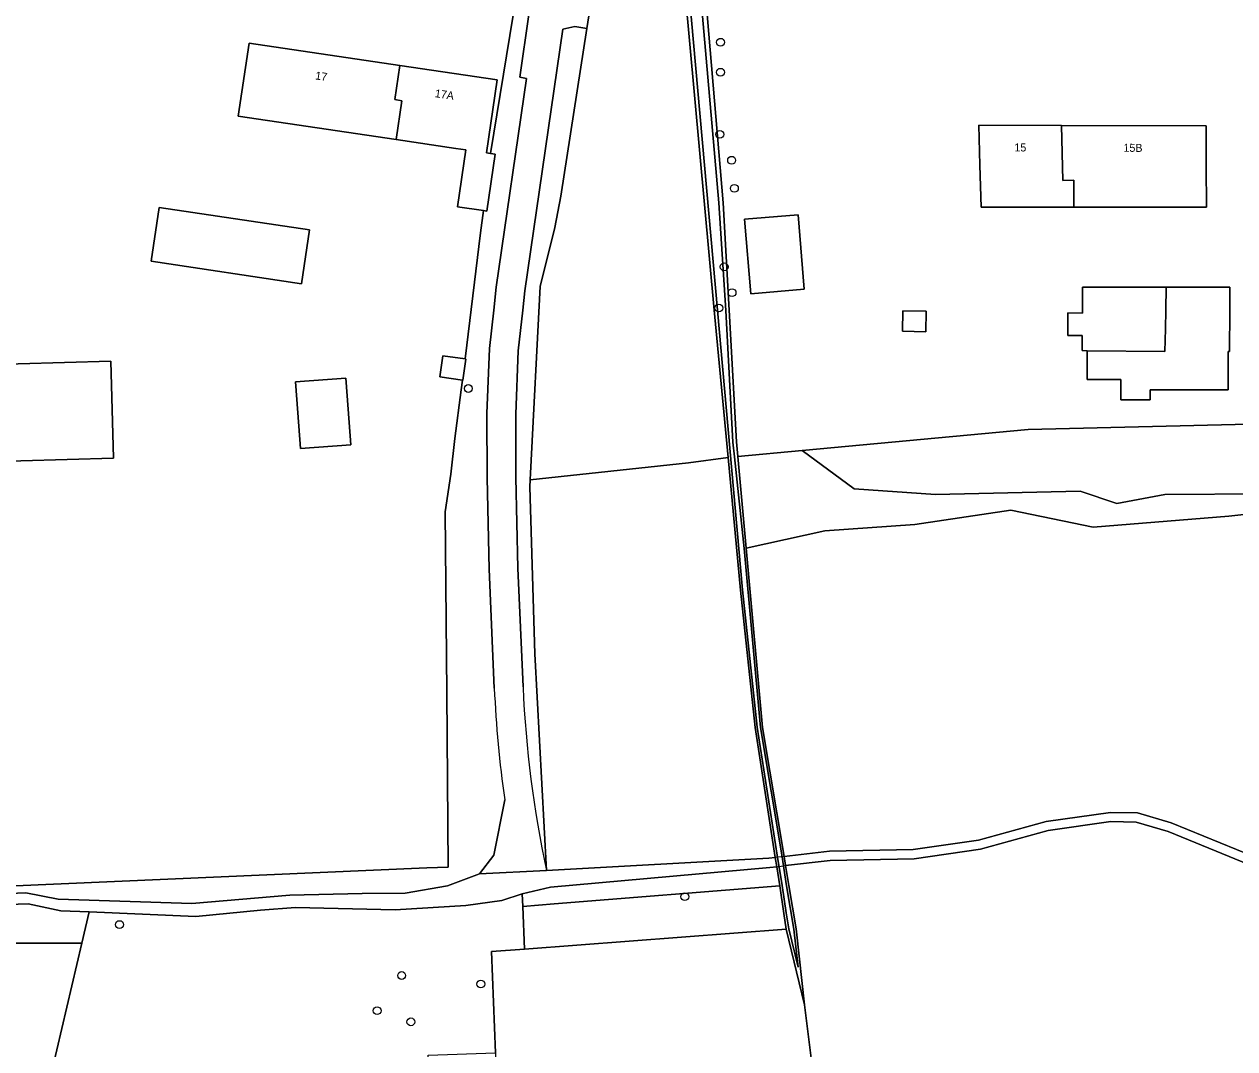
# Model space of a CAD drawing. Extents: x 162510 to 163918, y 388494 to 389774.
# Drawn here: x 162616.6 to 162767.9, y 388907.7 to 389035.7 of the extents above; entities that cross this region are included whole.
import ezdxf

# ---------------------------------------------------------------- set-up
doc = ezdxf.new("R2010")
doc.units = 0
for name, color, linetype in [('IMGEO_Boom', 7, 'Continuous'), ('IMGEO_Erf', 7, 'Continuous'), ('IMGEO_Grasland_agrarisch', 7, 'Continuous'), ('IMGEO_Grasland_overig', 7, 'Continuous'), ('IMGEO_Groenvoorziening', 7, 'Continuous'), ('IMGEO_Hek', 7, 'Continuous'), ('IMGEO_Loofbos', 7, 'Continuous'), ('IMGEO_Oever', 7, 'Continuous'), ('IMGEO_Pand', 7, 'Continuous'), ('IMGEO_Pand_nummerreeks', 7, 'Continuous'), ('IMGEO_Rijbaan_lokaal_gesloten', 7, 'Continuous'), ('IMGEO_Rijbaan_lokaal_halfverhard', 7, 'Continuous'), ('IMGEO_Rijbaan_lokaal_onverhard', 7, 'Continuous'), ('IMGEO_Waterloop', 7, 'Continuous')]:
    doc.layers.add(name, color=color, linetype=linetype)

msp = doc.modelspace()

# ---------------------------------------------------------------- linework, layer by layer
at = {"layer": 'IMGEO_Boom'}
for centre in [(162703.65, 389033.47), (162703.64, 389029.72), (162703.56, 389021.96), (162705.03, 389018.72), (162705.38, 389015.21), (162704.1, 389005.4), (162705.09, 389002.17), (162703.44, 389000.25), (162672.12, 388990.19), (162699.18, 388926.67), (162628.52, 388923.18), (162663.79, 388916.81), (162673.68, 388915.75), (162660.72, 388912.42), (162664.94, 388911.02)]:
    msp.add_circle(centre, 0.489, dxfattribs=at)
at = {"layer": 'IMGEO_Erf'}
for points in [[(162663.55, 389030.58), (162675.73, 389028.77), (162674.38, 389019.65), (162674.91, 389019.57), (162678.51, 389041.74), (162678.36, 389043.46), (162678.63, 389045.93)], [(162614.58, 388927.98), (162666.94, 388930.26), (162669.61, 388930.37), (162669.42, 388952.14), (162669.22, 388974.79), (162669.94, 388979.5), (162670.45, 388983.96), (162671.23, 388990.04), (162671.38, 388991.23), (162668.55, 388991.63), (162668.93, 388994.29), (162671.71, 388993.89), (162673.66, 389009.65), (162674, 389012.43), (162670.77, 389012.9), (162671.81, 389020.03), (162670.57, 389020.21), (162663.1, 389021.32), (162643.36, 389024.24), (162644.71, 389033.37), (162663.55, 389030.58)]]:
    msp.add_lwpolyline(points, dxfattribs=at)
for points in [[(162686.13, 389044.35), (162685.88, 389043.41), (162685.83, 389042.01), (162686.33, 389040.71), (162687.77, 389040.48), (162686.95, 389035.21), (162683.69, 389014.23), (162682.95, 389010.32), (162681.09, 389002.93), (162679.91, 388979.62), (162679.87, 388978.79), (162699.64, 388980.89), (162704.58, 388981.58), (162702.83, 389000), (162698.61, 389046.48), (162692.16, 389046.72), (162688.55, 389045.49), (162686.9, 389045.33)], [(162770.17, 389041.8), (162769.26, 389041.78), (162764.94, 389041.67), (162762.37, 389041.61), (162743.97, 389041.23), (162741.47, 389041.26), (162723.17, 389042.73), (162708.72, 389044.45), (162703.43, 389045.08), (162701.26, 389045.33), (162703.97, 389013.41), (162704.72, 389000), (162705.65, 388983.52), (162705.82, 388981.68), (162713.87, 388982.43), (162742.1, 388985.07), (162771.44, 388985.76), (162771.12, 389000)], [(162735.92, 389023.09), (162746.26, 389023.06), (162764.35, 389023.01), (162764.37, 389018.01), (162764.39, 389012.86), (162747.8, 389012.87), (162736.21, 389012.87), (162736.06, 389018.09)], [(162651.27, 389003.29), (162632.47, 389006.11), (162633.47, 389012.82), (162652.27, 389010.01)], [(162713.34, 389011.92), (162714.12, 389002.59), (162707.43, 389002.03), (162706.65, 389011.36)], [(162759.37, 389002.84), (162767.29, 389002.84), (162767.29, 389000), (162767.28, 388994.8), (162767.11, 388994.8), (162767.11, 388990.02), (162757.34, 388990.02), (162757.34, 388988.78), (162753.67, 388988.78), (162753.67, 388991.31), (162749.46, 388991.32), (162749.46, 388994.92), (162748.86, 388994.93), (162748.86, 388996.83), (162747.05, 388996.83), (162747.05, 388999.63), (162748.9, 388999.62), (162748.9, 389000), (162748.91, 389002.85)], [(162726.4, 388997.34), (162726.45, 388999.91), (162729.35, 388999.85), (162729.3, 388997.29)], [(162627.44, 388993.6), (162627.78, 388981.47), (162610.37, 388980.99), (162610.03, 388993.12)], [(162656.81, 388991.5), (162657.1, 388987.61), (162657.42, 388983.16), (162651.14, 388982.7), (162650.81, 388987.15), (162650.53, 388991.04)]]:
    msp.add_lwpolyline(points, close=True, dxfattribs=at)
at = {"layer": 'IMGEO_Grasland_agrarisch'}
msp.add_lwpolyline([(162710.49, 388931.57), (162707.98, 388947.83), (162706.16, 388965), (162704.58, 388981.58), (162699.64, 388980.89), (162679.87, 388978.79), (162679.83, 388977.88), (162680.42, 388957.01), (162681.91, 388929.94), (162709.68, 388931.47)], close=True, dxfattribs=at)
at = {"layer": 'IMGEO_Grasland_overig'}
for points in [[(162679.91, 388979.62), (162681.09, 389002.93), (162682.95, 389010.32), (162683.69, 389014.23), (162686.95, 389035.21), (162685.42, 389035.44), (162683.94, 389035.1), (162679.2, 389002.39), (162678.93, 389000), (162678.37, 388994.91), (162678.05, 388987), (162678.07, 388979.08), (162678.32, 388967.74), (162678.96, 388952.88)], [(162681.91, 388929.94), (162680.42, 388957.01), (162679.83, 388977.88), (162679.87, 388978.79), (162679.91, 388979.62)]]:
    msp.add_lwpolyline(points, dxfattribs=at)
for points in [[(162771.63, 388977.03), (162759.18, 388976.94), (162753.18, 388975.82), (162748.59, 388977.36), (162730.5, 388976.95), (162720.37, 388977.67), (162713.87, 388982.43), (162705.82, 388981.68), (162706.86, 388970.23), (162716.69, 388972.41), (162727.93, 388973.18), (162739.95, 388975), (162750.24, 388972.84), (162767.18, 388974.22), (162771.68, 388974.74)], [(162679.15, 388920.12), (162711.87, 388922.6), (162711.57, 388924.58), (162711.04, 388928.02), (162682.87, 388925.77), (162678.93, 388925.46)], [(162624.73, 388924.76), (162621.18, 388924.91), (162617.1, 388925.78), (162600.99, 388925.22), (162598.94, 388924.91), (162594.58, 388923.48), (162585.28, 388919.42), (162574.62, 388915.42), (162562.97, 388909.61), (162563.08, 388907.3), (162564.14, 388907.35), (162579.19, 388908.49), (162582.54, 388908.67), (162586.02, 388909.21), (162589.2, 388911.23), (162591.28, 388913.31), (162595.02, 388915.56), (162602.02, 388918.9), (162607.31, 388919.84), (162614.86, 388920.84), (162623.8, 388920.84)]]:
    msp.add_lwpolyline(points, close=True, dxfattribs=at)
msp.add_arc((162817.58, 388959.03), 138.76, 182.5435, 192.1018, dxfattribs=at)
at = {"layer": 'IMGEO_Groenvoorziening'}
for points in [[(162678.51, 389041.74), (162674.91, 389019.57), (162675.47, 389019.49), (162674.43, 389012.36), (162674, 389012.43), (162673.66, 389009.65), (162671.71, 388993.89), (162671.83, 388993.87), (162671.45, 388991.22), (162671.38, 388991.23), (162671.23, 388990.04), (162670.45, 388983.96), (162669.94, 388979.5), (162669.22, 388974.79), (162669.42, 388952.14), (162669.61, 388930.37), (162666.94, 388930.26), (162614.58, 388927.98)], [(162675.31, 389000), (162675.62, 389002.84), (162679.41, 389028.93), (162678.56, 389029.1), (162679.69, 389036.94)], [(162675.36, 388952.72), (162674.72, 388967.62), (162674.46, 388979.04), (162674.45, 388987.07), (162674.78, 388995.18), (162675.31, 389000)], [(162600.93, 388926.51), (162616.81, 388927.16), (162620.85, 388926.35), (162637.57, 388925.81), (162649.8, 388926.85), (162658.85, 388927.06), (162664.24, 388927.09), (162669.52, 388928.04), (162673.53, 388929.52), (162675.3, 388931.84), (162676.67, 388938.79)]]:
    msp.add_lwpolyline(points, dxfattribs=at)
for points in [[(162713.87, 388982.43), (162720.37, 388977.67), (162730.5, 388976.95), (162748.59, 388977.36), (162753.18, 388975.82), (162759.18, 388976.94), (162771.63, 388977.03), (162771.44, 388985.76), (162742.1, 388985.07)], [(162714.16, 388913.17), (162711.87, 388922.6), (162679.15, 388920.12), (162675.02, 388919.81), (162675.53, 388907.17), (162677.2, 388865.09), (162720.77, 388860.13)]]:
    msp.add_lwpolyline(points, close=True, dxfattribs=at)
msp.add_arc((162817.7, 388959.04), 142.47, 182.544, 188.1712, dxfattribs=at)
at = {"layer": 'IMGEO_Hek'}
for points in [[(162670.45, 388983.96), (162671.23, 388990.04)], [(162669.94, 388979.5), (162669.22, 388974.79), (162669.42, 388952.14)], [(162669.42, 388952.14), (162669.61, 388930.37), (162666.94, 388930.26)], [(162666.94, 388930.26), (162614.58, 388927.98)], [(162682.87, 388925.77), (162711.04, 388928.02)], [(162678.93, 388925.46), (162682.87, 388925.77)]]:
    msp.add_lwpolyline(points, dxfattribs=at)
at = {"layer": 'IMGEO_Loofbos'}
for points in [[(162717.28, 388932.34), (162727.74, 388932.58), (162735.9, 388933.72), (162744.35, 388936.06), (162752.38, 388937.21), (162755.76, 388937.15), (162759.98, 388935.89), (162774.27, 388930.05), (162780.17, 388928.65), (162779.73, 388931.61), (162777.31, 388948.04), (162777.42, 388954.51), (162773.99, 388957.61), (162771.8, 388969.76), (162771.68, 388974.74), (162767.18, 388974.22), (162750.24, 388972.84), (162739.95, 388975), (162727.93, 388973.18), (162716.69, 388972.41), (162706.86, 388970.23), (162708.89, 388947.83), (162711.59, 388931.69)], [(162773.92, 388928.95), (162759.59, 388934.8), (162755.59, 388936), (162752.45, 388936.05), (162744.59, 388934.93), (162736.14, 388932.59), (162727.84, 388931.42), (162717.36, 388931.19), (162711.78, 388930.55), (162712.19, 388928.08), (162713.1, 388922.66), (162713.16, 388922.29), (162714.16, 388913.17), (162720.77, 388860.13), (162742.46, 388857.66), (162798.24, 388863.43), (162799.04, 388869.27), (162799.08, 388869.54), (162788.74, 388870.61), (162788.35, 388873.03), (162780.35, 388927.41)], [(162709.8, 388930.32), (162682.38, 388927.84), (162678.87, 388927.02), (162678.93, 388925.46), (162682.87, 388925.77), (162711.04, 388928.02), (162710.67, 388930.42)], [(162623.8, 388920.84), (162620.04, 388904.86), (162667.1, 388906.56), (162667.1, 388906.86), (162675.53, 388907.17), (162675.02, 388919.81), (162679.15, 388920.12), (162678.93, 388925.46), (162678.87, 388927.02), (162676.3, 388926.18), (162671.81, 388925.58), (162662.99, 388925.04), (162650.5, 388925.3), (162646.15, 388924.99), (162638.07, 388924.19), (162624.73, 388924.76)], [(162573.16, 388903.16), (162620.04, 388904.86), (162623.8, 388920.84), (162614.86, 388920.84), (162607.31, 388919.84), (162602.02, 388918.9), (162595.02, 388915.56), (162591.28, 388913.31), (162589.2, 388911.23), (162586.02, 388909.21), (162582.54, 388908.67), (162579.19, 388908.49), (162564.14, 388907.35), (162564.26, 388902.98), (162570.6, 388903.11)]]:
    msp.add_lwpolyline(points, close=True, dxfattribs=at)
at = {"layer": 'IMGEO_Oever'}
for points in [[(162705.82, 388981.68), (162705.65, 388983.52), (162704.72, 389000), (162703.97, 389013.41), (162701.26, 389045.33), (162698.61, 389046.48), (162702.83, 389000), (162704.58, 388981.58), (162706.16, 388965), (162707.98, 388947.83), (162710.49, 388931.57), (162710.67, 388930.42), (162711.04, 388928.02), (162711.57, 388924.58), (162711.87, 388922.6), (162714.16, 388913.17), (162713.16, 388922.29), (162713.1, 388922.66), (162712.19, 388928.08), (162711.78, 388930.55), (162711.59, 388931.69), (162708.89, 388947.83), (162706.86, 388970.23)], [(162711.3, 388931.91), (162711.89, 388928.03), (162712.79, 388922.61), (162712.86, 388922.24), (162713.34, 388917.85), (162712.17, 388922.65), (162711.87, 388924.63), (162711.35, 388928.07), (162710.71, 388931.84), (162708.23, 388947.87), (162706.41, 388965.03), (162703.27, 388999.99), (162699.2, 389045.57), (162700.69, 389044.87), (162703.45, 389013.38), (162704.29, 388999.94), (162705.19, 388983.48), (162705.41, 388981.63), (162706.61, 388970.21), (162708.64, 388947.8)]]:
    msp.add_lwpolyline(points, close=True, dxfattribs=at)
at = {"layer": 'IMGEO_Pand'}
for points in [[(162663.1, 389021.32), (162663.8, 389026.17), (162662.94, 389026.3), (162663.55, 389030.58), (162644.71, 389033.37), (162643.36, 389024.24)], [(162663.1, 389021.32), (162670.57, 389020.21), (162671.81, 389020.03), (162670.77, 389012.9), (162674, 389012.43), (162674.43, 389012.36), (162675.47, 389019.49), (162674.91, 389019.57), (162674.38, 389019.65), (162675.73, 389028.77), (162663.55, 389030.58), (162662.94, 389026.3), (162663.8, 389026.17)], [(162747.8, 389012.87), (162747.81, 389016.22), (162746.43, 389016.18), (162746.26, 389023.06), (162735.92, 389023.09), (162736.06, 389018.09), (162736.21, 389012.87)], [(162747.8, 389012.87), (162764.39, 389012.86), (162764.37, 389018.01), (162764.35, 389023.01), (162746.26, 389023.06), (162746.43, 389016.18), (162747.81, 389016.22)], [(162651.27, 389003.29), (162652.27, 389010.01), (162633.47, 389012.82), (162632.47, 389006.11)], [(162713.34, 389011.92), (162706.65, 389011.36), (162707.43, 389002.03), (162714.12, 389002.59)], [(162759.37, 389002.84), (162748.91, 389002.85), (162748.9, 389000), (162748.9, 388999.62), (162747.05, 388999.63), (162747.05, 388996.83), (162748.86, 388996.83), (162748.86, 388994.93), (162749.46, 388994.92), (162759.18, 388994.83), (162759.25, 388997.67), (162759.3, 389000)], [(162759.37, 389002.84), (162759.3, 389000), (162759.25, 388997.67), (162759.18, 388994.83), (162749.46, 388994.92), (162749.46, 388991.32), (162753.67, 388991.31), (162753.67, 388988.78), (162757.34, 388988.78), (162757.34, 388990.02), (162767.11, 388990.02), (162767.11, 388994.8), (162767.28, 388994.8), (162767.29, 389000), (162767.29, 389002.84)], [(162726.4, 388997.34), (162729.3, 388997.29), (162729.35, 388999.85), (162726.45, 388999.91)], [(162671.71, 388993.89), (162668.93, 388994.29), (162668.55, 388991.63), (162671.38, 388991.23), (162671.45, 388991.22), (162671.83, 388993.87)], [(162627.44, 388993.6), (162610.03, 388993.12), (162610.37, 388980.99), (162627.78, 388981.47)], [(162656.81, 388991.5), (162650.53, 388991.04), (162650.81, 388987.15), (162651.14, 388982.7), (162657.42, 388983.16), (162657.1, 388987.61)]]:
    msp.add_lwpolyline(points, close=True, dxfattribs=at)
at = {"layer": 'IMGEO_Rijbaan_lokaal_gesloten'}
msp.add_lwpolyline([(162711.59, 388931.69), (162710.49, 388931.57), (162710.67, 388930.42), (162711.78, 388930.55)], close=True, dxfattribs=at)
at = {"layer": 'IMGEO_Rijbaan_lokaal_halfverhard'}
msp.add_lwpolyline([(162780.35, 388927.41), (162780.17, 388928.65), (162774.27, 388930.05), (162759.98, 388935.89), (162755.76, 388937.15), (162752.38, 388937.21), (162744.35, 388936.06), (162735.9, 388933.72), (162727.74, 388932.58), (162717.28, 388932.34), (162711.59, 388931.69), (162711.78, 388930.55), (162717.36, 388931.19), (162727.84, 388931.42), (162736.14, 388932.59), (162744.59, 388934.93), (162752.45, 388936.05), (162755.59, 388936), (162759.59, 388934.8), (162773.92, 388928.95)], close=True, dxfattribs=at)
at = {"layer": 'IMGEO_Rijbaan_lokaal_onverhard'}
for points in [[(162683.94, 389035.1), (162685.42, 389035.44), (162686.95, 389035.21), (162687.77, 389040.48), (162686.33, 389040.71), (162685.83, 389042.01), (162685.88, 389043.41), (162686.13, 389044.35), (162686.76, 389046.15), (162687.19, 389047.16)], [(162681.77, 389045.67), (162680.7, 389037.81), (162679.69, 389036.94), (162678.56, 389029.1), (162679.41, 389028.93), (162675.62, 389002.84), (162675.31, 389000), (162674.78, 388995.18), (162674.45, 388987.07), (162674.46, 388979.04), (162674.72, 388967.62), (162675.36, 388952.72)], [(162678.96, 388952.88), (162678.32, 388967.74), (162678.07, 388979.08), (162678.05, 388987), (162678.37, 388994.91), (162678.93, 389000), (162679.2, 389002.39), (162683.94, 389035.1)], [(162676.67, 388938.79), (162675.3, 388931.84), (162673.53, 388929.52), (162681.91, 388929.94)], [(162600.99, 388925.22), (162617.1, 388925.78), (162621.18, 388924.91), (162624.73, 388924.76), (162638.07, 388924.19), (162646.15, 388924.99), (162650.5, 388925.3), (162662.99, 388925.04), (162671.81, 388925.58), (162676.3, 388926.18), (162678.87, 388927.02), (162682.38, 388927.84), (162709.8, 388930.32), (162710.67, 388930.42), (162710.49, 388931.57), (162709.68, 388931.47), (162681.91, 388929.94), (162673.53, 388929.52), (162669.52, 388928.04), (162664.24, 388927.09), (162658.85, 388927.06), (162649.8, 388926.85), (162637.57, 388925.81), (162620.85, 388926.35), (162616.81, 388927.16), (162600.93, 388926.51)]]:
    msp.add_lwpolyline(points, dxfattribs=at)
for centre, radius, start, end in [((162817.7, 388959.04), 142.47, 182.544, 188.1712), ((162817.58, 388959.03), 138.76, 182.5435, 192.1018)]:
    msp.add_arc(centre, radius, start, end, dxfattribs=at)
at = {"layer": 'IMGEO_Waterloop'}
msp.add_lwpolyline([(162704.29, 388999.94), (162703.45, 389013.38), (162700.69, 389044.87), (162699.2, 389045.57), (162703.27, 388999.99), (162706.41, 388965.03), (162708.23, 388947.87), (162710.71, 388931.84), (162711.35, 388928.07), (162711.87, 388924.63), (162712.17, 388922.65), (162713.34, 388917.85), (162712.86, 388922.24), (162712.79, 388922.61), (162711.89, 388928.03), (162711.3, 388931.91), (162708.64, 388947.8), (162706.61, 388970.21), (162705.41, 388981.63), (162705.19, 388983.48)], close=True, dxfattribs=at)

# ---------------------------------------------------------------- texts
at = {"layer": 'IMGEO_Pand_nummerreeks'}
for s, rotation, p in [('17', 351.6263, (162652.94, 389028.84)), ('17A', 351.5234, (162667.89, 389026.62)), ('15', 0.0671, (162740.38, 389019.82)), ('15B', 359.7086, (162754.01, 389019.78))]:
    msp.add_text(s, height=1, rotation=rotation, dxfattribs=at).set_placement(p)

doc.saveas('drawing.dxf')
